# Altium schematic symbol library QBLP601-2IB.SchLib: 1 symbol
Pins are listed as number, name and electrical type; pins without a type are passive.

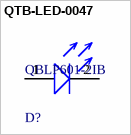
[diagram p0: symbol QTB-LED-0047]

## QTB-LED-0047
designator D?, comment QBLP601-2IB
LED BLUE CLEAR 0603 SMD; Manufacturer: QT Brightek (QTB); Lens Size: 0.8mm; Luminous Intensity: 95mcd; Test Current: 20mA; Lens Color: Colorless; Lens Style: Flat; Forward Voltage: 2.9V; Wavelength - Dominant: 465nm
footprint QBLP601-2IB-MFG
pins: 1 ANODE (+), 2 CATHODE (-)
